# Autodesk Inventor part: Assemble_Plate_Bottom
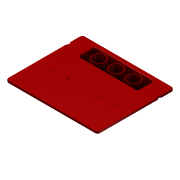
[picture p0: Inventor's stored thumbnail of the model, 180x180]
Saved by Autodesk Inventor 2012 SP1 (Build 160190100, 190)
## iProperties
Created: 2005-12
Part Number: Assemble_Plate_Bottom
Document SubType Name: Modeling
Designer: t_munrn
Density: 1 g/cm^3
Material: Default
Author: t_munrn
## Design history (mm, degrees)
sketch "Sketch1"
  geometry: L1 (-225, 187.5)-(225, 187.5); L2 (225, 187.5)-(225, -187.5); L3 (225, -187.5)-(-225, -187.5); L4 (-225, -187.5)-(-225, 187.5); L5 (-225, -187.5)-(225, 187.5); 2 further points
  constraints: 10 end point, 2 parallel, 1 coincident, 1 horizontal, 1 midpoint, 1 perpendicular
  dimensions: "d0" = 450 distance of L1.start L1.end; "d1" = 375 distance between parallel lines of L3 L1
extrude "Extrusion1" new body sketch "Sketch1" distance "d2" = 10; taper "d3" = 0 deg
fillet "Fillet1" dims "d4" = 12
sketch "Sketch2"
  geometry: L1 (225, 175.5)-(225, -175.5) reference; L2 (-213, 187.5)-(213, 187.5) reference; C1 r 11 at (231, 117.5)
  constraints: 1 centre point
  dimensions: "d5" = 22 diameter of C1; "d6" = 70 distance from line of L2 C1.centre; "d7" = 6 distance from line of L1 C1.centre
extrude "Extrusion2" cut sketch "Sketch2" stored distance "d8" = 16; taper "d9" = 0 deg
mirror "Mirror1"
fillet "Fillet2" dims "d10" = 6
workplane "Work Plane1"
  workaxis "Work Axis1"
  workaxis "Work Axis2"
sketch "Sketch4"
  geometry: L1 (-194, -56.768)-(-194, -5.768) reference; L2 (188, -62.768)-(-188, -62.768) reference; L3 (-188, 0.232)-(188, 0.232) reference; L4 (194, -5.768)-(194, -56.768) reference; A1 r 6 centre (-188, -56.768) between (-194, -56.768) and (-188, -62.768) reference; A2 r 6 centre (-188, -5.768) between (-188, 0.232) and (-194, -5.768) reference; A3 r 6 centre (188, -5.768) between (194, -5.768) and (188, 0.232) reference; A4 r 6 centre (188, -56.768) between (188, -62.768) and (194, -56.768) reference; 1 further point
  constraints: 8 end point, 8 point on circle, 4 centre point, 2 horizontal, 2 vertical, 16 other
extrude "Extrusion3" join sketch "Sketch4" distance "d11" = 22; taper "d12" = 0 deg
sketch "Sketch5"
  geometry: C1 r 10 at (150, -31.268) reference; C2 r 10 at (75, -31.268) reference; C3 r 10 at (0, -31.268) reference; C4 r 10 at (-75, -31.268) reference; C5 r 10 at (-150, -31.268) reference; C6 r 10.5 at (-150, -31.268); C7 r 10.5 at (-75, -31.268); C8 r 10.5 at (0, -31.268); C9 r 10.5 at (75, -31.268); C10 r 10.5 at (150, -31.268); 1 further point
  constraints: 10 centre point, 4 equal radius, 10 other
  dimensions: "d13" = 0.5 radial gap between concentric circles of C6 C5
extrude "Extrusion4" cut sketch "Sketch5" stored distance "d14" = 22; taper "d15" = -5 deg
sketch "Sketch6"
  geometry: L1 (-194, -56.768)-(-194, -5.768) reference; L2 (188, -62.768)-(-188, -62.768) reference; L3 (194, -5.768)-(194, -56.768) reference; L4 (-188, 0.232)-(188, 0.232) reference; L5 (-191, -56.768)-(-191, -5.768); L6 (-188, -2.768)-(188, -2.768); L7 (191, -5.768)-(191, -56.768); L8 (188, -59.768)-(-188, -59.768); C1 r 10.5 at (150, -31.268) reference; C2 r 10.5 at (-150, -31.268) reference; C3 r 10.5 at (-75, -31.268) reference; C4 r 10.5 at (0, -31.268) reference; C5 r 10.5 at (75, -31.268) reference; C6 r 13.5 at (-150, -31.268); C7 r 13.5 at (-75, -31.268); C8 r 13.5 at (0, -31.268); C9 r 13.5 at (75, -31.268); C10 r 13.5 at (150, -31.268); A1 r 6 centre (-188, -5.768) between (-188, 0.232) and (-194, -5.768) reference; A2 r 6 centre (-188, -56.768) between (-194, -56.768) and (-188, -62.768) reference; A3 r 6 centre (188, -56.768) between (188, -62.768) and (194, -56.768) reference; A4 r 6 centre (188, -5.768) between (194, -5.768) and (188, 0.232) reference; A5 r 3 centre (-188, -56.768) between (-191, -56.768) and (-188, -59.768); A6 r 3 centre (-188, -5.768) between (-188, -2.768) and (-191, -5.768); A7 r 3 centre (188, -5.768) between (191, -5.768) and (188, -2.768); A8 r 3 centre (188, -56.768) between (188, -59.768) and (191, -56.768); 1 further point
  constraints: 9 centre point, 8 end point, 8 point on circle, 4 equal radius, 7 other
  dimensions: "d16" = 3 radial gap between concentric circles of C2 C6; "d17" = 3 distance between parallel lines of L2 L8 (= d16)
extrude "Extrusion5" cut sketch "Sketch6" distance "d18" = 18; taper "d19" = -3 deg
sketch "Sketch7"
  geometry: C1 r 10.5 at (-150, -31.268) reference; C2 r 10.5 at (-75, -31.268) reference; C3 r 10.5 at (0, -31.268) reference; C4 r 10.5 at (75, -31.268) reference; C5 r 10.5 at (150, -31.268) reference; 1 further point
hole "Hole1" sketch "Sketch7" at (150, -31.268), (75, -31.268), (0, -31.268), (-75, -31.268), (-150, -31.268) diameter "d20" = 6; stored, may be unused: countersink angle "d24" = 90 deg, drill point angle "d26" = 118 deg; dims "d21" = 6, "d22" = 4, "d23" = 2, "d25" = 8
chamfer "Chamfer1" distance "d27" = 1; stored, may be unused: second distance "d28" = 2, angle "d29" = 60 deg
sketch "Sketch8"
  geometry: L1 (150, 158.732)-(150, 98.732) reference; L2 (135, 83.732)-(-135, 83.732) reference; L3 (-150, 98.732)-(-150, 158.732) reference; L4 (-135, 173.732)-(135, 173.732) reference; L5 (155, 98.732)-(155, 158.732) reference; L6 (-135, 78.732)-(135, 78.732) reference; L7 (-155, 158.732)-(-155, 98.732) reference; L8 (135, 178.732)-(-135, 178.732) reference; A1 r 15 centre (135, 158.732) between (150, 158.732) and (135, 173.732) reference; A2 r 15 centre (135, 98.732) between (135, 83.732) and (150, 98.732) reference; A3 r 15 centre (-135, 98.732) between (-150, 98.732) and (-135, 83.732) reference; A4 r 15 centre (-135, 158.732) between (-135, 173.732) and (-150, 158.732) reference; A5 r 20 centre (135, 98.732) between (135, 78.732) and (155, 98.732) reference; A6 r 20 centre (-135, 98.732) between (-155, 98.732) and (-135, 78.732) reference; A7 r 20 centre (-135, 158.732) between (-135, 178.732) and (-155, 158.732) reference; A8 r 20 centre (135, 158.732) between (155, 158.732) and (135, 178.732) reference; 1 further point
  constraints: 16 end point, 16 point on circle, 8 centre point, 4 horizontal, 4 vertical, 32 other
extrude "Extrusion6" join sketch "Sketch8" distance "d30" = 44; taper "d31" = 0 deg
extrude "Extrusion7" join sketch "Sketch8" distance "d32" = 33; taper "d33" = 0 deg
sketch "Sketch9"
  geometry: L1 (150, 158.732)-(150, 98.732) reference; L2 (-135, 173.732)-(135, 173.732) reference; L3 (-150, 98.732)-(-150, 158.732) reference; L4 (135, 83.732)-(-135, 83.732) reference; L5 (145, 158.732)-(145, 98.732); L6 (135, 88.732)-(-135, 88.732); L7 (-145, 98.732)-(-145, 158.732); L8 (-135, 168.732)-(135, 168.732); A1 r 15 centre (135, 158.732) between (150, 158.732) and (135, 173.732) reference; A2 r 15 centre (-135, 158.732) between (-135, 173.732) and (-150, 158.732) reference; A3 r 15 centre (-135, 98.732) between (-150, 98.732) and (-135, 83.732) reference; A4 r 15 centre (135, 98.732) between (135, 83.732) and (150, 98.732) reference; A5 r 10 centre (135, 158.732) between (145, 158.732) and (135, 168.732); A6 r 10 centre (135, 98.732) between (135, 88.732) and (145, 98.732); A7 r 10 centre (-135, 98.732) between (-145, 98.732) and (-135, 88.732); A8 r 10 centre (-135, 158.732) between (-135, 168.732) and (-145, 158.732); 1 further point
  constraints: 8 end point, 8 point on circle, 4 centre point, 7 other
  dimensions: "d34" = 5 distance between parallel lines of L2 L8
extrude "Extrusion8" cut sketch "Sketch9" distance "d35" = 6; taper "d36" = -5 deg
sketch "Sketch10"
  geometry: L1 (-145, 98.732)-(-145, 158.732) reference; L2 (-135, 168.732)-(135, 168.732) reference; C1 r 27.5 at (0, 128.732); 3 further points
  constraints: 2 midpoint, 1 centre point, 1 horizontal alignment, 1 vertical alignment
  dimensions: "d37" = 55 diameter of C1
extrude "Extrusion9" cut sketch "Sketch10" stored distance "d38" = 6; taper "d39" = 0 deg
pattern_linear "Rectangular Pattern1" dims "d42" = 85
sketch "Sketch11"
  geometry: L1 (-135, 168.207)-(135, 168.207) reference; L2 (144.475, 158.732)-(144.475, 98.732) reference; L3 (135, 89.257)-(-135, 89.257) reference; L4 (-144.475, 98.732)-(-144.475, 158.732) reference; C1 r 27.5 at (85, 128.732) reference; C2 r 27.5 at (-85, 128.732) reference; C3 r 27.5 at (0, 128.732) reference; C4 r 31.5 at (85, 128.732); C5 r 31.5 at (0, 128.732); C6 r 31.5 at (-85, 128.732); A1 r 9.475 centre (135, 158.732) between (144.475, 158.732) and (135, 168.207) reference; A2 r 9.475 centre (135, 98.732) between (135, 89.257) and (144.475, 98.732) reference; A3 r 9.475 centre (-135, 98.732) between (-144.475, 98.732) and (-135, 89.257) reference; A4 r 9.475 centre (-135, 158.732) between (-135, 168.207) and (-144.475, 158.732) reference; 1 further point
  constraints: 3 centre point, 2 equal radius
  dimensions: "d43" = 4 radial gap between concentric circles of C1 C4
extrude "Extrusion10" cut sketch "Sketch11" distance "d44" = 40; taper "d45" = -5 deg
fillet "Fillet3" dims "d46" = 5
chamfer "Chamfer3" distance "d50" = 1; stored, may be unused: second distance "d51" = 2, angle "d52" = 60 deg
chamfer "Chamfer4" distance "d53" = 1; stored, may be unused: second distance "d54" = 2, angle "d55" = 60 deg
body "Solid1"
